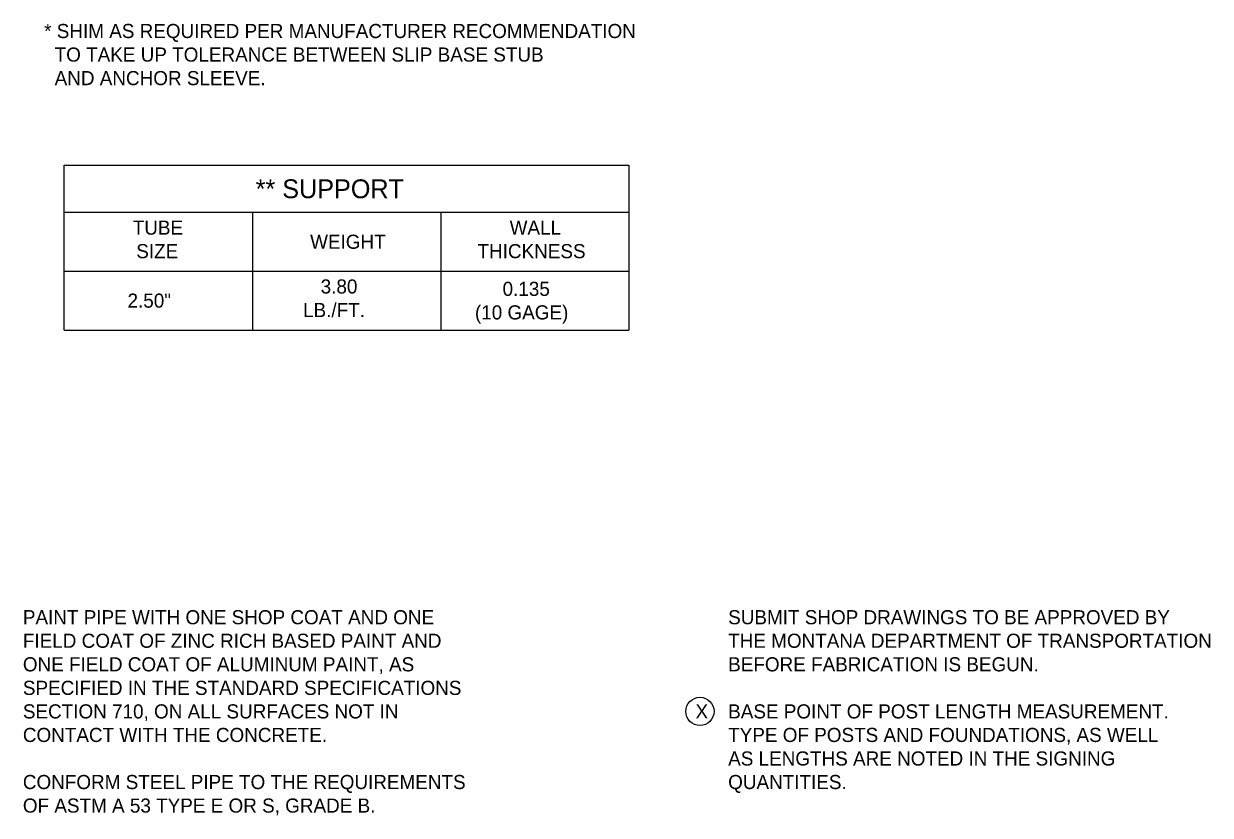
# Model space of a CAD drawing. Extents: x 49940 to 50043, y 49986 to 50011.
# Drawn here: x 49956.84 to 49961.89, y 49988.72 to 49992.08 of the extents above; entities that cross this region are included whole.
import ezdxf

# ---------------------------------------------------------------- set-up
doc = ezdxf.new("R2010")
doc.units = 0
doc.layers.add('Level 2', color=7, linetype='Continuous')

msp = doc.modelspace()

# ---------------------------------------------------------------- linework, layer by layer
at = {"layer": 'Level 2'}
for p, q in [((49957.0158, 49991.4787), (49959.4158, 49991.4787)), ((49957.0158, 49990.7787), (49957.0158, 49991.4787)), ((49959.4158, 49991.4787), (49959.4158, 49990.7787)), ((49957.0158, 49991.2787), (49959.4158, 49991.2787)), ((49957.8158, 49991.2787), (49957.8158, 49990.7787)), ((49958.6158, 49991.2787), (49958.6158, 49990.7787)), ((49957.0158, 49991.0287), (49959.4158, 49991.0287)), ((49957.8158, 49991.0285), (49957.8158, 49991.0285)), ((49958.6155, 49991.0285), (49958.6155, 49991.0285)), ((49958.1741, 49990.8786), (49958.1741, 49990.8786)), ((49957.0158, 49990.7787), (49959.4158, 49990.7787))]:
    msp.add_line(p, q, dxfattribs=at)
msp.add_circle((49959.7173, 49989.159), 0.06, dxfattribs=at)

# ---------------------------------------------------------------- texts
for s, height, p in [('* SHIM AS REQUIRED PER MANUFACTURER RECOMMENDATION ', 0.06, (49956.931, 49992.0188)), ('  TO TAKE UP TOLERANCE BETWEEN SLIP BASE STUB ', 0.06, (49956.931, 49991.9188)), ('  AND ANCHOR SLEEVE.', 0.06, (49956.931, 49991.8188)), ('** SUPPORT', 0.08, (49957.8297, 49991.3387)), ('TUBE', 0.06, (49957.3074, 49991.1838)), ('WALL', 0.06, (49958.9088, 49991.1838)), ('WEIGHT', 0.06, (49958.0611, 49991.1237)), ('SIZE', 0.06, (49957.3223, 49991.0838)), ('THICKNESS', 0.06, (49958.7723, 49991.0838)), ('3.80', 0.06, (49958.1058, 49990.9338)), ('0.135', 0.06, (49958.8788, 49990.9237)), ('2.50"', 0.06, (49957.2852, 49990.8737)), ('LB./FT.', 0.06, (49958.031, 49990.8338)), ('(10 GAGE)', 0.06, (49958.7614, 49990.8237)), ('PAINT PIPE WITH ONE SHOP COAT AND ONE', 0.06, (49956.8405, 49989.529)), ('SUBMIT SHOP DRAWINGS TO BE APPROVED BY', 0.06, (49959.8373, 49989.529)), ('FIELD COAT OF ZINC RICH BASED PAINT AND', 0.06, (49956.8405, 49989.429)), ('THE MONTANA DEPARTMENT OF TRANSPORTATION', 0.06, (49959.8373, 49989.429)), ('ONE FIELD COAT OF ALUMINUM PAINT, AS', 0.06, (49956.8405, 49989.329)), ('BEFORE FABRICATION IS BEGUN.', 0.06, (49959.8373, 49989.329)), ('SPECIFIED IN THE STANDARD SPECIFICATIONS', 0.06, (49956.8405, 49989.229)), ('SECTION 710, ON ALL SURFACES NOT IN', 0.06, (49956.8405, 49989.129)), ('X', 0.06, (49959.6984, 49989.129)), ('BASE POINT OF POST LENGTH MEASUREMENT.', 0.06, (49959.8373, 49989.129)), ('CONTACT WITH THE CONCRETE.', 0.06, (49956.8405, 49989.029)), ('TYPE OF POSTS AND FOUNDATIONS, AS WELL', 0.06, (49959.8373, 49989.029)), ('AS LENGTHS ARE NOTED IN THE SIGNING', 0.06, (49959.8373, 49988.929)), ('CONFORM STEEL PIPE TO THE REQUIREMENTS', 0.06, (49956.8405, 49988.829)), ('QUANTITIES.', 0.06, (49959.8373, 49988.829)), ('OF ASTM A 53 TYPE E OR S, GRADE B.', 0.06, (49956.8405, 49988.729))]:
    msp.add_text(s, height=height, dxfattribs=at).set_placement(p)

doc.saveas('drawing.dxf')
